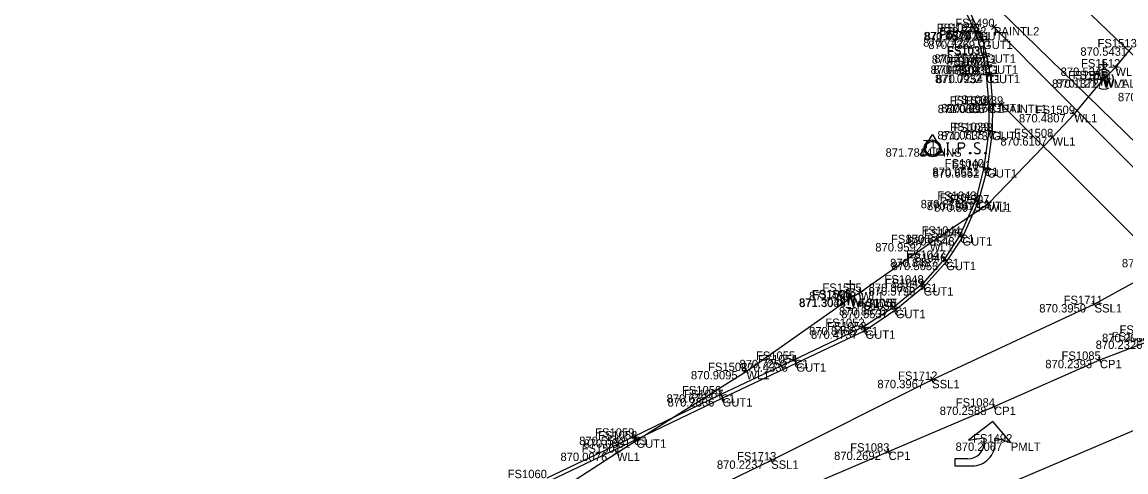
# Model space of a CAD drawing. Extents: x 1469677 to 1493262, y 375219 to 389293.
# Drawn here: x 1479434.8 to 1479592.9, y 379878.6 to 379943 of the extents above; entities that cross this region are included whole.
import ezdxf

# ---------------------------------------------------------------- set-up
doc = ezdxf.new("R2010")
doc.units = 0
for name, color, linetype in [('Building', 7, 'Continuous'), ('DR_X_Drive_Pipe', 7, 'Continuous'), ('DV_X_Property_Line', 7, 'Continuous'), ('DV_X_Text', 7, 'Continuous'), ('GK_Visualization', 7, 'Continuous'), ('PNTELEV', 7, 'Continuous'), ('PNTNO', 7, 'Continuous'), ('RD_P_Text', 7, 'Continuous'), ('RD_X_RR_1', 7, 'Continuous'), ('RW_P_Esmt_SW', 7, 'Continuous'), ('RW_P_Esmt_TMP', 7, 'Continuous'), ('SV_X_Mon_Cells_Found', 7, 'Continuous'), ('UT_X_Electric', 7, 'Continuous'), ('VG_X_Flower_Bed', 7, 'Continuous')]:
    doc.layers.add(name, color=color, linetype=linetype)

msp = doc.modelspace()

# ---------------------------------------------------------------- linework, layer by layer
at = {"layer": 'Building'}
for points in [[(1479636.37, 379879.56), (1479574.01, 379942.24)], [(1479627.79, 379878.69), (1479575.12, 379931.13)], [(1479601.1, 379887.48), (1479569.29, 379873.92)]]:
    msp.add_lwpolyline(points, dxfattribs=at)
at = {"layer": 'DR_X_Drive_Pipe'}
for points in [[(1479473.22, 380054.88), (1479498.74, 380029.97), (1479514.51, 380014.09), (1479533.45, 379996.74), (1479556, 379974.32), (1479574.86, 379956.27), (1479584.4, 379947.43), (1479599.6, 379932.82), (1479630.11, 379903.78), (1479644.77, 379889.72), (1479654.21, 379882.36), (1479664.27, 379872.63), (1479692.51, 379845.85), (1479712.67, 379826.69), (1479730.74, 379809.85), (1479753.15, 379788.31), (1479771.84, 379770.54), (1479781.68, 379761.1)], [(1479451.52, 379837.18), (1479469.62, 379848.28), (1479481.98, 379856.4), (1479496.24, 379865.93), (1479520, 379881.31), (1479538.56, 379893), (1479553.44, 379903.41), (1479554.94, 379904.33), (1479564.84, 379911.31), (1479573.24, 379917), (1479582.4, 379926.47), (1479585.52, 379929.79), (1479589.65, 379934.74), (1479591.41, 379936.45), (1479593.78, 379939.33)]]:
    msp.add_lwpolyline(points, dxfattribs=at)
at = {"layer": 'DV_X_Property_Line'}
for p, q in [((1479563.47, 379923.88), (1479565.2, 379926.88)), ((1479565.2, 379926.88), (1479566.93, 379923.88)), ((1479565.2, 379924.88), (1479565.2, 379924.88)), ((1479566.93, 379923.88), (1479563.47, 379923.88))]:
    msp.add_line(p, q, dxfattribs=at)
msp.add_circle((1479565.2, 379924.88), 1, dxfattribs=at)
at = {"layer": 'PNTELEV'}
for p, q in [((1479574.36, 379941.89), (1479573.66, 379942.6)), ((1479573.66, 379941.89), (1479574.36, 379942.59)), ((1479574.01, 379942.24), (1479574.01, 379942.24)), ((1479571.82, 379941.73), (1479570.92, 379941.3)), ((1479571.15, 379941.97), (1479571.58, 379941.06)), ((1479572.12, 379940.78), (1479571.16, 379940.48)), ((1479571.37, 379941.52), (1479571.37, 379941.52)), ((1479572.32, 379941.75), (1479571.41, 379941.33)), ((1479571.49, 379941.11), (1479571.79, 379940.15)), ((1479571.64, 379940.63), (1479571.64, 379940.63)), ((1479571.66, 379942), (1479572.07, 379941.09)), ((1479571.86, 379941.54), (1479571.86, 379941.54)), ((1479572.23, 379940.75), (1479572.65, 379939.84)), ((1479572.89, 379940.5), (1479571.99, 379940.08)), ((1479572.44, 379940.29), (1479572.44, 379940.29)), ((1479572.88, 379938.35), (1479571.93, 379938.05)), ((1479572.25, 379938.68), (1479572.55, 379937.72)), ((1479573.38, 379938.44), (1479572.4, 379938.22)), ((1479572.4, 379938.2), (1479572.4, 379938.2)), ((1479572.78, 379938.82), (1479573, 379937.84)), ((1479572.89, 379938.33), (1479572.89, 379938.33)), ((1479573.22, 379936.84), (1479572.24, 379936.63)), ((1479572.62, 379937.22), (1479572.84, 379936.25)), ((1479573.7, 379936.85), (1479572.72, 379936.65)), ((1479572.73, 379936.74), (1479572.73, 379936.74)), ((1479572.85, 379935.91), (1479572.99, 379934.92)), ((1479573.11, 379937.24), (1479573.31, 379936.26)), ((1479573.21, 379936.75), (1479573.21, 379936.75)), ((1479573.38, 379935.9), (1479573.59, 379934.92)), ((1479591.05, 379936.1), (1479591.76, 379936.8)), ((1479591.06, 379936.81), (1479591.75, 379936.09)), ((1479591.41, 379936.45), (1479591.41, 379936.45)), ((1479573.41, 379935.49), (1479572.42, 379935.35)), ((1479572.92, 379935.42), (1479572.92, 379935.42)), ((1479573.98, 379935.52), (1479573, 379935.31)), ((1479573.49, 379935.41), (1479573.49, 379935.41)), ((1479589.26, 379935.06), (1479590.03, 379934.42)), ((1479589.33, 379934.35), (1479589.97, 379935.12)), ((1479589.65, 379934.74), (1479589.65, 379934.74)), ((1479573.78, 379931.16), (1479572.79, 379931.07)), ((1479573.24, 379931.61), (1479573.33, 379930.62)), ((1479573.29, 379931.12), (1479573.29, 379931.12)), ((1479574.32, 379931.28), (1479573.32, 379931.2)), ((1479573.78, 379931.74), (1479573.86, 379930.74)), ((1479573.82, 379931.24), (1479573.82, 379931.24)), ((1479574.77, 379930.77), (1479575.48, 379931.48)), ((1479575.48, 379930.78), (1479574.77, 379931.48)), ((1479575.12, 379931.13), (1479575.12, 379931.13)), ((1479585.15, 379930.13), (1479585.88, 379929.44)), ((1479585.17, 379929.42), (1479585.86, 379930.15)), ((1479585.52, 379929.79), (1479585.52, 379929.79)), ((1479573.78, 379927.36), (1479572.78, 379927.36)), ((1479574.26, 379927.24), (1479573.26, 379927.25)), ((1479573.28, 379927.86), (1479573.28, 379926.86)), ((1479573.28, 379927.36), (1479573.28, 379927.36)), ((1479573.76, 379927.75), (1479573.75, 379926.75)), ((1479573.76, 379927.25), (1479573.76, 379927.25)), ((1479582.04, 379926.82), (1479582.76, 379926.12)), ((1479582.06, 379926.11), (1479582.75, 379926.83)), ((1479582.4, 379926.47), (1479582.4, 379926.47)), ((1479573.08, 379922.06), (1479572.09, 379922.2)), ((1479572.65, 379922.63), (1479572.52, 379921.63)), ((1479573.54, 379921.82), (1479572.55, 379921.95)), ((1479572.59, 379922.13), (1479572.59, 379922.13)), ((1479573.11, 379922.38), (1479572.98, 379921.39)), ((1479573.05, 379921.89), (1479573.05, 379921.89)), ((1479571.89, 379917.38), (1479570.92, 379917.63)), ((1479571.53, 379917.99), (1479571.28, 379917.02)), ((1479572.25, 379917.1), (1479571.29, 379917.37)), ((1479571.4, 379917.5), (1479571.4, 379917.5)), ((1479571.9, 379917.72), (1479571.64, 379916.75)), ((1479571.77, 379917.23), (1479571.77, 379917.23)), ((1479572.83, 379916.72), (1479573.65, 379917.29)), ((1479572.96, 379917.42), (1479573.52, 379916.59)), ((1479573.24, 379917), (1479573.24, 379917)), ((1479569.61, 379912.31), (1479568.7, 379912.72)), ((1479569.36, 379912.97), (1479568.95, 379912.05)), ((1479569.95, 379911.96), (1479569.04, 379912.37)), ((1479569.16, 379912.51), (1479569.16, 379912.51)), ((1479569.7, 379912.62), (1479569.29, 379911.7)), ((1479569.5, 379912.16), (1479569.5, 379912.16)), ((1479564.44, 379911.02), (1479565.25, 379911.6)), ((1479564.56, 379911.72), (1479565.13, 379910.9)), ((1479564.84, 379911.31), (1479564.84, 379911.31)), ((1479567.37, 379908.79), (1479566.53, 379909.32)), ((1479567.22, 379909.48), (1479566.68, 379908.63)), ((1479567.44, 379909.06), (1479566.89, 379908.23)), ((1479566.95, 379909.06), (1479566.95, 379909.06)), ((1479567.58, 379908.37), (1479566.75, 379908.92)), ((1479567.17, 379908.64), (1479567.17, 379908.64)), ((1479564.23, 379905.19), (1479563.48, 379905.85)), ((1479564.18, 379905.9), (1479563.52, 379905.15)), ((1479554.52, 379904.07), (1479555.37, 379904.59)), ((1479554.68, 379904.75), (1479555.2, 379903.9)), ((1479554.94, 379904.33), (1479554.94, 379904.33)), ((1479564.32, 379904.67), (1479563.57, 379905.33)), ((1479564.28, 379905.38), (1479563.61, 379904.63)), ((1479563.85, 379905.52), (1479563.85, 379905.52)), ((1479563.94, 379905), (1479563.94, 379905)), ((1479553.03, 379903.12), (1479553.85, 379903.7)), ((1479553.16, 379903.82), (1479553.73, 379903)), ((1479553.44, 379903.41), (1479553.44, 379903.41)), ((1479588.88, 379902.82), (1479588, 379902.34)), ((1479588.68, 379902.14), (1479588.2, 379903.02)), ((1479560.08, 379902.46), (1479559.31, 379901.83)), ((1479560.01, 379901.76), (1479559.38, 379902.54)), ((1479560.34, 379902.07), (1479559.56, 379901.44)), ((1479560.27, 379901.37), (1479559.64, 379902.15)), ((1479559.69, 379902.15), (1479559.69, 379902.15)), ((1479559.95, 379901.76), (1479559.95, 379901.76)), ((1479588.44, 379902.58), (1479588.44, 379902.58)), ((1479555.77, 379899.58), (1479554.94, 379899.03)), ((1479555.63, 379898.89), (1479555.08, 379899.73)), ((1479556.02, 379899.09), (1479555.2, 379898.53)), ((1479555.89, 379898.4), (1479555.33, 379899.23)), ((1479555.35, 379899.31), (1479555.35, 379899.31)), ((1479555.61, 379898.81), (1479555.61, 379898.81)), ((1479545.87, 379894.81), (1479544.97, 379894.38)), ((1479545.63, 379894.15), (1479545.21, 379895.05)), ((1479588.74, 379894.39), (1479589.65, 379894.8)), ((1479588.99, 379895.05), (1479589.4, 379894.14)), ((1479538.13, 379892.73), (1479538.98, 379893.27)), ((1479538.29, 379893.42), (1479538.82, 379892.58)), ((1479546.16, 379894.32), (1479545.26, 379893.89)), ((1479545.42, 379894.6), (1479545.42, 379894.6)), ((1479545.93, 379893.65), (1479545.5, 379894.56)), ((1479545.71, 379894.1), (1479545.71, 379894.1)), ((1479589.2, 379894.6), (1479589.2, 379894.6)), ((1479538.56, 379893), (1479538.56, 379893)), ((1479565.62, 379891.94), (1479564.72, 379891.51)), ((1479565.38, 379891.27), (1479564.96, 379892.18)), ((1479565.17, 379891.73), (1479565.17, 379891.73)), ((1479535.11, 379889.2), (1479534.69, 379890.11)), ((1479535.35, 379889.87), (1479534.45, 379889.44)), ((1479535.59, 379889.33), (1479534.69, 379888.9)), ((1479534.9, 379889.66), (1479534.9, 379889.66)), ((1479535.36, 379888.66), (1479534.93, 379889.57)), ((1479535.14, 379889.11), (1479535.14, 379889.11)), ((1479573.58, 379887.7), (1479574.5, 379888.1)), ((1479573.84, 379888.36), (1479574.23, 379887.44)), ((1479574.04, 379887.9), (1479574.04, 379887.9)), ((1479522.85, 379883.81), (1479521.95, 379883.38)), ((1479522.62, 379883.15), (1479522.18, 379884.05)), ((1479523.02, 379882.76), (1479522.59, 379883.66)), ((1479523.26, 379883.43), (1479522.35, 379882.99)), ((1479522.4, 379883.6), (1479522.4, 379883.6)), ((1479522.8, 379883.21), (1479522.8, 379883.21)), ((1479519.58, 379881.03), (1479520.42, 379881.58)), ((1479519.73, 379881.73), (1479520.27, 379880.89)), ((1479520, 379881.31), (1479520, 379881.31)), ((1479542.33, 379879.75), (1479541.89, 379880.64)), ((1479558.47, 379881.26), (1479559.39, 379881.66)), ((1479558.73, 379881.92), (1479559.12, 379881)), ((1479558.93, 379881.46), (1479558.93, 379881.46)), ((1479542.56, 379880.42), (1479541.66, 379879.97)), ((1479542.11, 379880.2), (1479542.11, 379880.2))]:
    msp.add_line(p, q, dxfattribs=at)
at = {"layer": 'PNTNO'}
for p, q in [((1479589.76, 379936.17), (1479589.76, 379937.44)), ((1479590.4, 379936.81), (1479589.13, 379936.81)), ((1479589.76, 379934.77), (1479589.76, 379934.77)), ((1479553.49, 379904.75), (1479553.49, 379906.02)), ((1479554.12, 379905.39), (1479552.85, 379905.39)), ((1479553.49, 379903.35), (1479553.49, 379903.35))]:
    msp.add_line(p, q, dxfattribs=at)
for points in [[(1479589.13, 379935.59), (1479589.44, 379933.87), (1479589.76, 379935.59), (1479590.08, 379933.87), (1479590.4, 379935.59)], [(1479552.85, 379904.17), (1479553.17, 379902.45), (1479553.49, 379904.17), (1479553.81, 379902.45), (1479554.12, 379904.17)]]:
    msp.add_lwpolyline(points, dxfattribs=at)
for centre, start, end in [((1479589.76, 379934.77), 60.0184, 120.0157), ((1479589.76, 379934.77), 150.0184, 209.9816), ((1479589.76, 379934.77), 330.0184, 29.9816), ((1479589.76, 379934.77), 239.9843, 299.9816), ((1479553.48, 379903.35), 60.0184, 120.0157), ((1479553.48, 379903.35), 150.0184, 209.9816), ((1479553.48, 379903.35), 330.0184, 29.9816), ((1479553.48, 379903.35), 239.9843, 299.9816)]:
    msp.add_arc(centre, 1.4, start, end, dxfattribs=at)
at = {"layer": 'RD_P_Text'}
for points in [[(1479570, 379944.36), (1479571.37, 379941.52), (1479571.64, 379940.63), (1479572.4, 379938.2), (1479572.73, 379936.74), (1479572.92, 379935.42), (1479573.29, 379931.12), (1479573.28, 379927.36), (1479572.59, 379922.13), (1479571.4, 379917.5), (1479569.16, 379912.51), (1479566.95, 379909.06), (1479563.85, 379905.52), (1479559.69, 379902.15), (1479555.35, 379899.31), (1479545.42, 379894.6), (1479534.9, 379889.66), (1479522.4, 379883.6), (1479509.98, 379877.66)], [(1479570.39, 379944.78), (1479571.86, 379941.54), (1479572.44, 379940.29), (1479572.89, 379938.33), (1479573.21, 379936.75), (1479573.49, 379935.41), (1479573.82, 379931.24), (1479573.76, 379927.25), (1479573.05, 379921.89), (1479571.77, 379917.23), (1479569.5, 379912.16), (1479567.17, 379908.64), (1479563.94, 379905), (1479559.95, 379901.76), (1479555.61, 379898.81), (1479545.71, 379894.1), (1479535.14, 379889.11), (1479522.8, 379883.21), (1479510.32, 379877.21)]]:
    msp.add_lwpolyline(points, dxfattribs=at)
at = {"layer": 'RD_X_RR_1'}
msp.add_lwpolyline([(1479441.79, 379822.02), (1479455, 379829.68), (1479469.11, 379838.41), (1479482.14, 379846), (1479493.54, 379852.15), (1479505.24, 379858.04), (1479517.8, 379863.73), (1479530.74, 379869.52), (1479544.65, 379875.38), (1479558.93, 379881.46), (1479574.04, 379887.9), (1479589.2, 379894.6), (1479596.44, 379897.36)], dxfattribs=at)
at = {"layer": 'RW_P_Esmt_TMP'}
for p, q in [((1479573.87, 379885.76), (1479570.35, 379883.09)), ((1479576.43, 379882.76), (1479573.87, 379885.76)), ((1479568.43, 379882.76), (1479568.43, 379882.76)), ((1479570.35, 379883.09), (1479572.59, 379883.42)), ((1479572.59, 379883.42), (1479572.59, 379882.72)), ((1479574.19, 379882.76), (1479574.19, 379883.42)), ((1479574.19, 379883.42), (1479576.43, 379882.76)), ((1479576.43, 379882.76), (1479576.43, 379882.76)), ((1479570.3, 379880.42), (1479568.43, 379880.42)), ((1479568.43, 379880.42), (1479568.43, 379879.42)), ((1479568.43, 379879.42), (1479570.91, 379879.42))]:
    msp.add_line(p, q, dxfattribs=at)
for centre, radius, end in [((1479570.3, 379882.72), 2.3, 0), ((1479570.91, 379882.71), 3.28, 0.9085)]:
    msp.add_arc(centre, radius, 270, end, dxfattribs=at)
at = {"layer": 'SV_X_Mon_Cells_Found'}
msp.add_lwpolyline([(1477164.63, 382297.85), (1479615.89, 379904.59), (1480413.41, 379159.22)], dxfattribs=at)
at = {"layer": 'UT_X_Electric'}
msp.add_lwpolyline([(1479823.04, 380000.22), (1479820.4, 379999.93), (1479798.15, 379991.17), (1479736.04, 379968.23), (1479710.11, 379956.45), (1479679.1, 379944.84), (1479664.16, 379939.68), (1479652.59, 379935.62), (1479645.23, 379932.51), (1479624.65, 379923.42), (1479621.96, 379921.49), (1479620.42, 379921.06), (1479600.28, 379909.05), (1479588.44, 379902.58), (1479565.17, 379891.73), (1479542.11, 379880.2), (1479514.62, 379866.87)], dxfattribs=at)
at = {"layer": 'VG_X_Flower_Bed'}
for points in [[(1479567.22, 379925.68), (1479567.57, 379925.68)], [(1479567.39, 379924.08), (1479567.39, 379925.68)], [(1479568.96, 379924.08), (1479568.96, 379925.68), (1479569.49, 379925.68), (1479569.54, 379925.67), (1479569.62, 379925.64), (1479569.65, 379925.62), (1479569.69, 379925.59), (1479569.73, 379925.53), (1479569.76, 379925.46), (1479569.79, 379925.36), (1479569.79, 379925.21), (1479569.77, 379925.16), (1479569.75, 379925.09), (1479569.71, 379925), (1479569.66, 379924.96), (1479569.63, 379924.94), (1479569.58, 379924.91), (1479569.49, 379924.9), (1479568.96, 379924.9)], [(1479571.97, 379925.56), (1479571.95, 379925.59), (1479571.91, 379925.62), (1479571.81, 379925.65), (1479571.69, 379925.68), (1479571.6, 379925.68), (1479571.57, 379925.68), (1479571.43, 379925.64), (1479571.31, 379925.56), (1479571.23, 379925.46), (1479571.21, 379925.36), (1479571.21, 379925.29), (1479571.23, 379925.19), (1479571.32, 379925.1), (1479571.92, 379924.72), (1479571.98, 379924.67), (1479572, 379924.62), (1479572.02, 379924.54), (1479572.02, 379924.47), (1479572.01, 379924.39), (1479572, 379924.34), (1479571.98, 379924.28), (1479571.96, 379924.23), (1479571.93, 379924.19), (1479571.9, 379924.15), (1479571.87, 379924.13), (1479571.82, 379924.1), (1479571.79, 379924.09), (1479571.69, 379924.08), (1479571.54, 379924.08), (1479571.44, 379924.1), (1479571.3, 379924.19), (1479571.21, 379924.27)], [(1479567.22, 379924.08), (1479567.57, 379924.08)], [(1479568.35, 379924.29), (1479568.41, 379924.29), (1479568.44, 379924.27), (1479568.47, 379924.22), (1479568.47, 379924.15), (1479568.44, 379924.1), (1479568.41, 379924.08), (1479568.35, 379924.08), (1479568.32, 379924.1), (1479568.29, 379924.15), (1479568.29, 379924.22), (1479568.32, 379924.27), (1479568.35, 379924.29)], [(1479570.6, 379924.29), (1479570.66, 379924.29), (1479570.69, 379924.27), (1479570.72, 379924.22), (1479570.72, 379924.15), (1479570.69, 379924.1), (1479570.66, 379924.08), (1479570.6, 379924.08), (1479570.57, 379924.1), (1479570.53, 379924.15), (1479570.53, 379924.22), (1479570.57, 379924.27), (1479570.6, 379924.29)], [(1479572.78, 379924.29), (1479572.84, 379924.29), (1479572.87, 379924.27), (1479572.9, 379924.22), (1479572.9, 379924.15), (1479572.87, 379924.1), (1479572.84, 379924.08), (1479572.78, 379924.08), (1479572.75, 379924.1), (1479572.72, 379924.15), (1479572.72, 379924.22), (1479572.75, 379924.27), (1479572.78, 379924.29)]]:
    msp.add_lwpolyline(points, dxfattribs=at)
msp.add_circle((1479565.2, 379924.88), 1.2, dxfattribs=at)

# ---------------------------------------------------------------- texts
at = {"layer": 'DV_X_Text'}
for s, p in [('870.5782', (1479566.24, 379941.04)), ('870.7422', (1479563.88, 379939.43)), ('870.7043', (1479563.96, 379940.34)), ('871.0574', (1479564.07, 379940.32)), ('870.7369', (1479564.62, 379939.09)), ('870.5431', (1479586.4, 379938.13)), ('870.7178', (1479565.11, 379937)), ('870.7136', (1479565.49, 379937.13)), ('870.7629', (1479564.94, 379935.54)), ('870.7504', (1479565.33, 379935.55)), ('870.5349', (1479583.57, 379935.25)), ('871.0932', (1479565.57, 379934.22)), ('870.7254', (1479565.74, 379934.21)), ('870.1372', (1479582.33, 379933.54)), ('870.1217', (1479582.93, 379933.57)), ('870.4543', (1479591.78, 379931.62)), ('871.0885', (1479565.96, 379929.92)), ('870.7216', (1479566.46, 379930.04)), ('870.6976', (1479567.23, 379929.93)), ('870.4807', (1479577.6, 379928.59)), ('871.0635', (1479565.92, 379926.16)), ('870.7173', (1479566.47, 379926.05)), ('870.6107', (1479574.95, 379925.27)), ('871.7814', (1479558.49, 379923.68)), ('870.9631', (1479565.19, 379920.93)), ('870.6552', (1479565.24, 379920.69)), ('870.8750', (1479563.52, 379916.3)), ('870.5981', (1479564.41, 379916.03)), ('870.5973', (1479565.45, 379915.8)), ('870.8427', (1479561.37, 379911.31)), ('870.5548', (1479561.68, 379910.96)), ('870.9592', (1479557.02, 379910.11)), ('870.8487', (1479559.14, 379907.86)), ('870.4064', (1479592.35, 379907.85)), ('870.5653', (1479559.35, 379907.44)), ('871.4506', (1479547.54, 379903.13)), ('870.5790', (1479556.05, 379903.8)), ('870.8675', (1479556.06, 379904.32)), ('871.3048', (1479546.08, 379902.21)), ('871.3034', (1479546.13, 379902.15)), ('870.8676', (1479551.82, 379900.95)), ('870.5537', (1479552.14, 379900.56)), ('870.3950', (1479580.51, 379901.38)), ('870.8465', (1479547.53, 379898.11)), ('870.4737', (1479547.81, 379897.61)), ('870.2680', (1479589.5, 379897.13)), ('870.2326', (1479588.59, 379896.16)), ('870.7250', (1479537.56, 379893.4)), ('870.4336', (1479537.79, 379892.9)), ('870.2393', (1479581.38, 379893.4)), ('870.9095', (1479530.61, 379891.8)), ('870.3967', (1479557.32, 379890.53)), ('870.6727', (1479527.12, 379888.46)), ('870.2836', (1479527.27, 379887.91)), ('870.2588', (1479566.25, 379886.7)), ('870.5542', (1479514.6, 379882.4)), ('870.0801', (1479515.23, 379882.01)), ('870.2067', (1479568.52, 379881.56)), ('870.0076', (1479511.92, 379880.11)), ('870.2692', (1479551.12, 379880.26)), ('870.2237', (1479534.33, 379879))]:
    msp.add_text(s, height=1.2, dxfattribs=at).set_placement(p)
at = {"layer": 'GK_Visualization'}
for s, p in [('PAINTL2', (1479574.01, 379941.04)), ('C1', (1479571.37, 379940.32)), ('C1', (1479571.64, 379939.43)), ('GUT1', (1479571.86, 379940.34)), ('GUT1', (1479572.44, 379939.09)), ('C1', (1479572.4, 379937)), ('GUT1', (1479572.89, 379937.13)), ('C1', (1479572.73, 379935.54)), ('GUT1', (1479573.21, 379935.55)), ('WL1', (1479591.41, 379935.25)), ('C1', (1479572.92, 379934.22)), ('GUT1', (1479573.49, 379934.21)), ('WL1', (1479589.65, 379933.54)), ('WVALVE', (1479589.76, 379933.57)), ('C1', (1479573.29, 379929.92)), ('GUT1', (1479573.82, 379930.04)), ('PAINTL1', (1479575.12, 379929.93)), ('WL1', (1479585.52, 379928.59)), ('C1', (1479573.28, 379926.16)), ('GUT1', (1479573.76, 379926.05)), ('WL1', (1479582.4, 379925.27)), ('IPINS', (1479565.2, 379923.68)), ('C1', (1479572.59, 379920.93)), ('GUT1', (1479573.05, 379920.69)), ('C1', (1479571.4, 379916.3)), ('GUT1', (1479571.77, 379916.03)), ('WL1', (1479573.24, 379915.8)), ('C1', (1479569.16, 379911.31)), ('GUT1', (1479569.5, 379910.96)), ('WL1', (1479564.84, 379910.11)), ('C1', (1479566.95, 379907.86)), ('GUT1', (1479567.17, 379907.44)), ('WL1', (1479554.94, 379903.13)), ('C1', (1479563.85, 379904.32)), ('GUT1', (1479563.94, 379903.8)), ('WL1', (1479553.44, 379902.21)), ('WVALVE', (1479553.49, 379902.15)), ('C1', (1479559.69, 379900.95)), ('GUT1', (1479559.95, 379900.56)), ('SSL1', (1479588.44, 379901.38)), ('C1', (1479555.35, 379898.11)), ('GUT1', (1479555.61, 379897.61)), ('C1', (1479545.42, 379893.4)), ('GUT1', (1479545.71, 379892.9)), ('CP1', (1479589.2, 379893.4)), ('WL1', (1479538.56, 379891.8)), ('SSL1', (1479565.17, 379890.53)), ('C1', (1479534.9, 379888.46)), ('GUT1', (1479535.14, 379887.91)), ('CP1', (1479574.04, 379886.7)), ('C1', (1479522.4, 379882.4)), ('GUT1', (1479522.8, 379882.01)), ('PMLT', (1479576.43, 379881.56)), ('WL1', (1479520, 379880.11)), ('CP1', (1479558.93, 379880.26)), ('SSL1', (1479542.11, 379879))]:
    msp.add_text(s, height=1.2, dxfattribs=at).set_placement(p)
at = {"layer": 'RW_P_Esmt_SW'}
for s, p in [('FS1026', (1479565.81, 379941.52)), ('FS1028', (1479566.37, 379941.54)), ('FS1490', (1479568.49, 379942.24)), ('FS1027', (1479566.16, 379940.63)), ('FS1029', (1479566.95, 379940.29)), ('FS1030', (1479567.27, 379938.33)), ('FS1031', (1479567.34, 379938.2)), ('FS1513', (1479588.86, 379939.33)), ('FS1032', (1479567.22, 379936.74)), ('FS1033', (1479567.69, 379936.75)), ('FS1512', (1479586.5, 379936.45)), ('FS1035', (1479567.4, 379935.42)), ('FS1034', (1479567.98, 379935.41)), ('FS1510', (1479584.63, 379934.74)), ('FS1511', (1479585.3, 379934.77)), ('FS1036', (1479567.69, 379931.12)), ('FS1037', (1479568.3, 379931.24)), ('FS1489', (1479569.72, 379931.13)), ('FS1509', (1479580.01, 379929.79)), ('FS1039', (1479567.75, 379927.36)), ('FS1038', (1479568.23, 379927.25)), ('FS1508', (1479576.9, 379926.47)), ('T1', (1479563.87, 379924.88)), ('FS1040', (1479566.97, 379922.13)), ('FS1041', (1479567.99, 379921.89)), ('FS1043', (1479565.9, 379917.5)), ('FS1042', (1479566.27, 379917.23)), ('FS1507', (1479567.74, 379917)), ('FS1044', (1479563.66, 379912.51)), ('FS1506', (1479559.27, 379911.31)), ('FS1045', (1479563.99, 379912.16)), ('FS1047', (1479561.44, 379909.06)), ('FS1046', (1479561.58, 379908.64)), ('FS1048', (1479558.33, 379905.52)), ('FS1049', (1479558.43, 379905)), ('FS1503', (1479547.94, 379903.41)), ('FS1504', (1479548, 379903.35)), ('FS1505', (1479549.45, 379904.33)), ('FS1050', (1479554.35, 379901.76)), ('FS1051', (1479554.65, 379902.15)), ('FS1711', (1479584, 379902.58)), ('FS1052', (1479549.87, 379899.31)), ('FS1053', (1479550.11, 379898.81)), ('FS1483', (1479592.01, 379898.33)), ('FS1086', (1479590.87, 379897.36)), ('FS1055', (1479539.92, 379894.6)), ('FS1054', (1479540.22, 379894.1)), ('FS1085', (1479583.7, 379894.6)), ('FS1502', (1479533.07, 379893)), ('FS1712', (1479560.29, 379891.73)), ('FS1056', (1479529.33, 379889.66)), ('FS1057', (1479529.64, 379889.11)), ('FS1084', (1479568.55, 379887.9)), ('FS1059', (1479516.89, 379883.6)), ('FS1058', (1479517.3, 379883.21)), ('FS1492', (1479571.03, 379882.76)), ('FS1501', (1479514.95, 379881.31)), ('FS1083', (1479553.43, 379881.46)), ('FS1713', (1479537.22, 379880.2)), ('FS1060', (1479504.36, 379877.66))]:
    msp.add_text(s, height=1.2, dxfattribs=at).set_placement(p)

doc.saveas('drawing.dxf')
